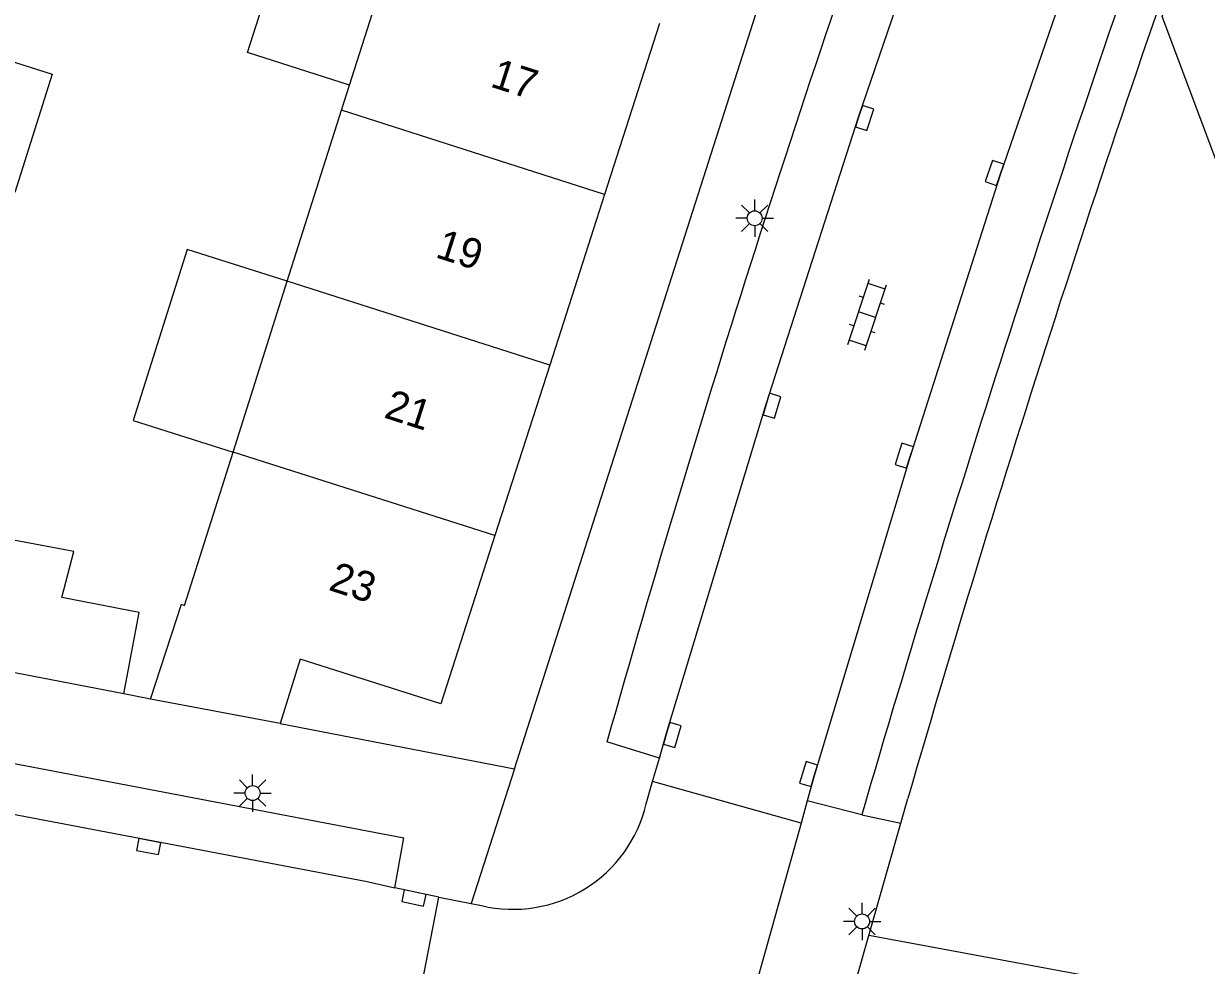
# Model space of a CAD drawing. Extents: x 124000 to 128010, y 398999 to 403000.
# Drawn here: x 127066.11 to 127105.67, y 399109.37 to 399140.87 of the extents above; entities that cross this region are included whole.
import ezdxf

# ---------------------------------------------------------------- set-up
doc = ezdxf.new("R2010")
doc.units = 0
for name, color, linetype in [('gg-afsc-faunaraster', 7, 'Continuous'), ('gg-afsc-muur', 7, 'Continuous'), ('gg-anno-huisnummerreeks BGT', 7, 'Continuous'), ('gg-bbg-bijgebouw', 7, 'Continuous'), ('gg-bbg-hoofdgebouw', 7, 'Continuous'), ('gg-bbg-luifel en loopbrug', 7, 'Continuous'), ('gg-bbg-tussenscheiding', 7, 'Continuous'), ('gg-knt-verharding', 7, 'Continuous'), ('gg-knt-verharding nz', 7, 'Continuous'), ('gt-grn-groengrens', 7, 'Continuous'), ('gt-grn-weggrens', 7, 'Continuous'), ('gt-symb-klinker verharding', 7, 'Continuous'), ('gt-symb-kolk', 7, 'Continuous'), ('gt-symb-lichtmast', 7, 'Continuous')]:
    doc.layers.add(name, color=color, linetype=linetype)

# ---------------------------------------------------------------- blocks, each defined once
blk = doc.blocks.new('gt0-KOLK')
at = {"layer": 'gt-symb-kolk'}
blk.add_lwpolyline([(0, 0), (0.375, 0), (0.375, 0.4), (-0.375, 0.4), (-0.375, 0), (0, 0)], dxfattribs=at)
blk = doc.blocks.new('gt0-LMAST')
at = {"layer": 'gt-symb-lichtmast'}
for p, q in [((-0.182, 0.173), (-0.447, 0.438)), ((-0.005, 0.246), (-0.005, 0.621)), ((0.172, 0.173), (0.437, 0.438)), ((-0.255, -0.004), (-0.63, -0.004)), ((-0.182, -0.181), (-0.447, -0.446)), ((-0.005, -0.254), (-0.005, -0.629)), ((0.437, -0.446), (0.172, -0.181)), ((0.245, -0.004), (0.62, -0.004))]:
    blk.add_line(p, q, dxfattribs=at)
blk.add_circle((-0.005, -0.004), 0.25, dxfattribs=at)
blk = doc.blocks.new('gt0-KL1')
at = {"layer": 'gt-symb-klinker verharding'}
for p, q in [((-0.5, 0.3), (-0.5, 0.45)), ((0.5, 0.3), (0.5, 0.45)), ((-1.15, 0.3), (1.15, 0.3)), ((-1, -0.3), (-1, 0.3)), ((0, -0.3), (0, 0.3)), ((1, -0.3), (1, 0.3)), ((-1.15, -0.3), (1.15, -0.3)), ((-0.5, -0.45), (-0.5, -0.3)), ((0.5, -0.45), (0.5, -0.3))]:
    blk.add_line(p, q, dxfattribs=at)

msp = doc.modelspace()

# ---------------------------------------------------------------- linework, layer by layer
at = {"layer": 'gg-afsc-faunaraster'}
msp.add_lwpolyline([(127115.99, 399109.666), (127104.195, 399141.114), (127107.149, 399149.639), (127110.428, 399158.481), (127113.661, 399166.893), (127117.1, 399175.328), (127120.484, 399183.469), (127125.35, 399194.525), (127128.514, 399201.504), (127133.259, 399201.299)], dxfattribs=at)
at = {"layer": 'gg-afsc-muur'}
msp.add_line((127070.359, 399118.269), (127069.456, 399118.456), dxfattribs=at)
at = {"layer": 'gg-bbg-bijgebouw'}
msp.add_lwpolyline([(127064.884, 399139.872), (127067.067, 399139.18), (127065.813, 399135.224)], dxfattribs=at)
at = {"layer": 'gg-bbg-hoofdgebouw'}
for p, q in [((127077.012, 399138.818), (127078.56, 399143.694)), ((127087.375, 399140.874), (127085.539, 399135.16)), ((127076.744, 399137.975), (127077.012, 399138.818)), ((127074.929, 399132.257), (127076.744, 399137.975)), ((127085.539, 399135.16), (127083.706, 399129.452)), ((127073.114, 399126.538), (127074.929, 399132.257)), ((127083.706, 399129.452), (127081.872, 399123.745)), ((127069.456, 399118.456), (127059.166, 399120.419)), ((127074.689, 399117.458), (127070.359, 399118.269))]:
    msp.add_line(p, q, dxfattribs=at)
for points in [[(127070.359, 399118.269), (127071.391, 399121.456), (127071.487, 399121.412), (127073.114, 399126.538)], [(127069.456, 399118.456), (127069.969, 399121.168), (127067.388, 399121.671), (127067.787, 399123.21), (127060.064, 399124.668)], [(127081.872, 399123.745), (127080.065, 399118.119), (127075.362, 399119.614), (127074.689, 399117.458)]]:
    msp.add_lwpolyline(points, dxfattribs=at)
at = {"layer": 'gg-bbg-luifel en loopbrug'}
for points in [[(127077.012, 399138.818), (127073.599, 399139.902), (127074.82, 399143.746), (127076.613, 399143.177), (127076.94, 399144.208), (127078.56, 399143.694)], [(127074.929, 399132.257), (127071.585, 399133.319), (127069.769, 399127.6), (127073.114, 399126.538)]]:
    msp.add_lwpolyline(points, dxfattribs=at)
at = {"layer": 'gg-bbg-tussenscheiding'}
for p, q in [((127085.539, 399135.16), (127076.744, 399137.975)), ((127083.706, 399129.452), (127074.929, 399132.257)), ((127081.872, 399123.745), (127073.114, 399126.538))]:
    msp.add_line(p, q, dxfattribs=at)
at = {"layer": 'gg-knt-verharding'}
for p, q in [((127082.527, 399115.948), (127093.976, 399151.763)), ((127074.689, 399117.458), (127082.527, 399115.948)), ((127087.378, 399116.303), (127085.62, 399116.841)), ((127087.14, 399115.517), (127087.378, 399116.303)), ((127092.114, 399114.125), (127087.14, 399115.517)), ((127092.316, 399114.874), (127092.114, 399114.125)), ((127094.145, 399114.403), (127092.316, 399114.874)), ((127095.454, 399114.127), (127095.689, 399114.951)), ((127094.381, 399110.372), (127095.454, 399114.127)), ((127078.521, 399111.96), (127078.829, 399113.638)), ((127080, 399111.65), (127078.521, 399111.96)), ((127079.038, 399106.742), (127080, 399111.65)), ((127094.018, 399109.072), (127094.381, 399110.372))]:
    msp.add_line(p, q, dxfattribs=at)
msp.add_lwpolyline([(127058, 399115.907), (127058.37, 399117.536), (127078.829, 399113.638)], dxfattribs=at)
for centre, radius, start, end in [((127568.814, 398980.394), 502.089, 160.29906, 164.23111), ((127639.289, 398957.299), 566, 160.30671, 163.82703), ((127674.362, 398945.308), 604.355, 160.551226, 163.752135)]:
    msp.add_arc(centre, radius, start, end, dxfattribs=at)
at = {"layer": 'gg-knt-verharding nz'}
for p, q in [((127058, 399115.907), (127077.545, 399112.182)), ((127086.934, 399114.768), (127087.14, 399115.517)), ((127077.545, 399112.182), (127078.521, 399111.96)), ((127080, 399111.65), (127081.084, 399111.435)), ((127081.084, 399111.435), (127081.43, 399111.366))]:
    msp.add_line(p, q, dxfattribs=at)
for points in [[(127087.378, 399116.303), (127087.617, 399117.132), (127090.951, 399128.146), (127094.052, 399137.78), (127097.903, 399149.046)], [(127102.69, 399147.15), (127102.48, 399146.574), (127098.773, 399135.813), (127095.758, 399126.357), (127092.556, 399115.71), (127092.316, 399114.874)], [(127092.114, 399114.125), (127089.966, 399106.444), (127087.866, 399098.751)]]:
    msp.add_lwpolyline(points, dxfattribs=at)
msp.add_arc((127082.482, 399115.818), 4.574, 256.7074, 346.7327, dxfattribs=at)
at = {"layer": 'gt-grn-groengrens'}
msp.add_line((127125.492, 399104.606), (127094.381, 399110.372), dxfattribs=at)
at = {"layer": 'gt-grn-weggrens'}
for p, q in [((127082.527, 399115.948), (127081.084, 399111.435)), ((127094.145, 399114.403), (127095.454, 399114.127))]:
    msp.add_line(p, q, dxfattribs=at)

# ---------------------------------------------------------------- block references
at = {"layer": 'gt-symb-klinker verharding', "rotation": 71.58316555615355}
msp.add_blockref('gt0-KL1', (127094.325, 399131.14), dxfattribs=at)
at = {"layer": 'gt-symb-kolk'}
for p, rotation in [((127094.052, 399137.78), -107.8188889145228), ((127098.773, 399135.813), 70.96692019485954), ((127090.951, 399128.146), -106.85839876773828), ((127095.758, 399126.357), 72.3076991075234), ((127087.617, 399117.132), -106.07917237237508), ((127092.556, 399115.71), 73.26783977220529), ((127070.258, 399113.144), -10.781616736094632), ((127079.205, 399111.818), 168.11724113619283)]:
    msp.add_blockref('gt0-KOLK', p, dxfattribs=dict(at, rotation=rotation))
at = {"layer": 'gt-symb-lichtmast'}
for p in [(127090.568, 399134.366), (127073.773, 399115.136), (127094.161, 399110.841)]:
    msp.add_blockref('gt0-LMAST', p, dxfattribs=at)

# ---------------------------------------------------------------- texts
at = {"layer": 'gg-anno-huisnummerreeks BGT'}
for s, p in [('17', (127081.682, 399138.774)), ('19', (127079.849, 399133.066)), ('21', (127078.126, 399127.704)), ('23', (127076.273, 399121.935))]:
    msp.add_text(s, height=1, rotation=342.2, dxfattribs=at).set_placement(p)

doc.saveas('drawing.dxf')
